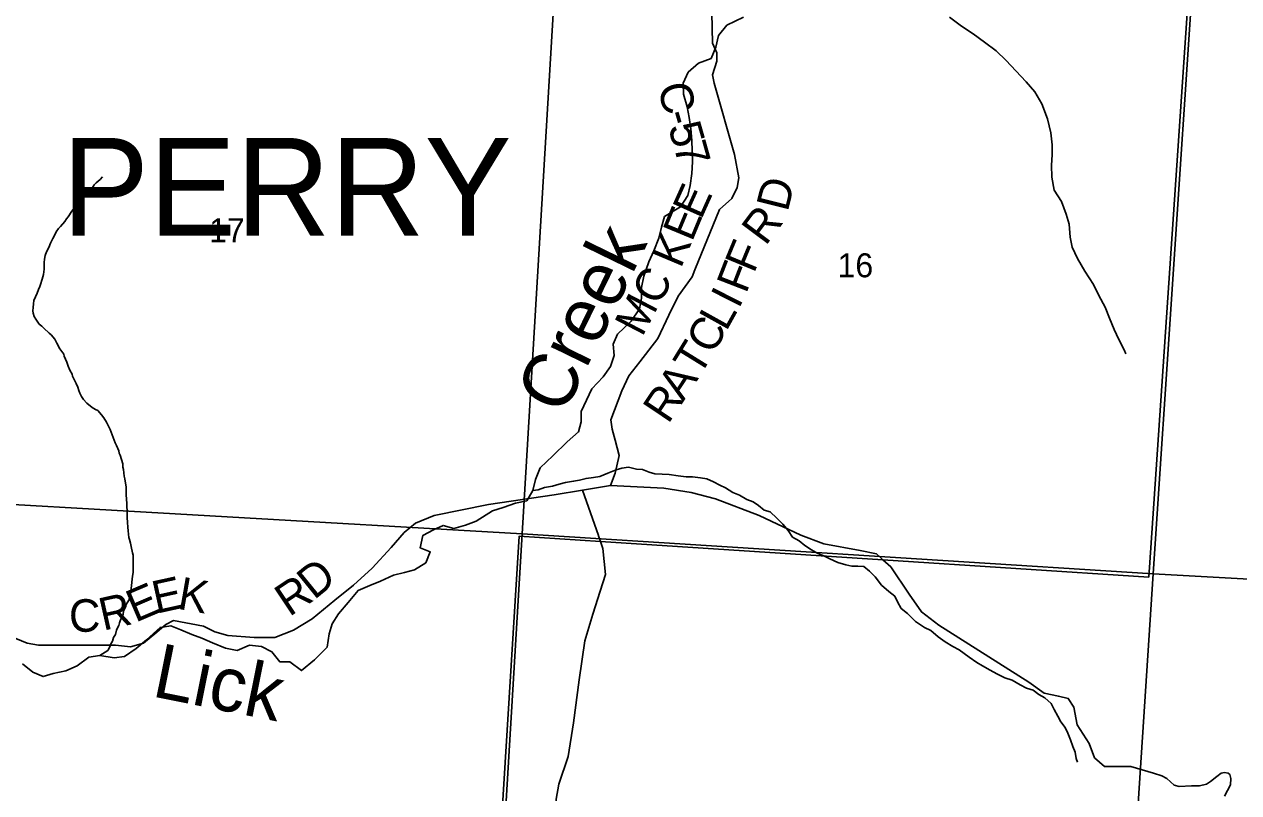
# Model space of a CAD drawing. Extents: x 1949938.81 to 1949945.61, y 152207.65 to 152214.09.
# Drawn here: x 1949940.583 to 1949942.704, y 152211.771 to 152213.113 of the extents above; entities that cross this region are included whole.
import ezdxf

# ---------------------------------------------------------------- set-up
doc = ezdxf.new("R2010")
doc.units = 0
for name, color, linetype in [('GM_X_County_Road', 7, 'Continuous'), ('GM_X_County_Road_Text', 7, 'Continuous'), ('GM_X_Minor_River', 7, 'Continuous'), ('GM_X_Minor_River_Text', 7, 'Continuous'), ('GM_X_Section', 7, 'Continuous'), ('GM_X_Section_Text', 7, 'Continuous'), ('GM_X_Township', 7, 'Continuous'), ('GM_X_Township_Road', 7, 'Continuous'), ('GM_X_Township_Text', 7, 'Continuous')]:
    doc.layers.add(name, color=color, linetype=linetype)

msp = doc.modelspace()

# ---------------------------------------------------------------- linework, layer by layer
at = {"layer": 'GM_X_County_Road'}
for points in [[(1949941.6066, 152212.3076), (1949941.6147, 152212.3293), (1949941.6219, 152212.3605), (1949941.6147, 152212.3869), (1949941.6099, 152212.4061), (1949941.6075, 152212.4228), (1949941.6267, 152212.4732), (1949941.6387, 152212.4996), (1949941.6579, 152212.5236), (1949941.6891, 152212.5644), (1949941.7083, 152212.6051), (1949941.7251, 152212.6387), (1949941.7371, 152212.6555), (1949941.7491, 152212.6723), (1949941.7539, 152212.6843), (1949941.7971, 152212.7898), (1949941.8186, 152212.809), (1949941.8282, 152212.8282), (1949941.8306, 152212.845), (1949941.8234, 152212.8857), (1949941.7875, 152213.0105), (1949941.7851, 152213.0248), (1949941.7923, 152213.0488), (1949941.7923, 152213.0632), (1949941.7851, 152213.08), (1949941.7823, 152213.1873)], [(1949940.5553, 152212.0457), (1949940.588, 152212.0326), (1949940.6077, 152212.0293), (1949940.742, 152212.0293), (1949940.7682, 152212.026), (1949940.7911, 152212.0326), (1949940.8107, 152212.049), (1949940.8304, 152212.0653), (1949940.8435, 152212.0719), (1949940.8959, 152212.0621), (1949940.9156, 152212.0522), (1949940.9385, 152212.0457), (1949940.9843, 152212.0424), (1949941.0204, 152212.0424), (1949941.0531, 152212.0555), (1949941.0859, 152212.0751), (1949941.1252, 152212.1079), (1949941.1579, 152212.1341), (1949941.1907, 152212.1636), (1949941.2234, 152212.1996), (1949941.2464, 152212.2258), (1949941.266, 152212.2421), (1949941.2988, 152212.2552), (1949941.3937, 152212.2749), (1949941.5084, 152212.2913), (1949941.558, 152212.2995), (1949941.6066, 152212.3076), (1949941.6998, 152212.3034), (1949941.7476, 152212.2958), (1949941.7898, 152212.2843), (1949941.8663, 152212.2556), (1949941.9391, 152212.2212), (1949941.9793, 152212.2058), (1949942.0425, 152212.1944), (1949942.0712, 152212.1886), (1949942.0825, 152212.1782), (1949942.0961, 152212.1657), (1949942.1285, 152212.1182)], [(1949942.1285, 152212.1182), (1949942.1497, 152212.0872), (1949942.1803, 152212.0642), (1949942.3373, 152211.9647), (1949942.3641, 152211.9455), (1949942.389, 152211.9398), (1949942.4062, 152211.936), (1949942.4158, 152211.9207), (1949942.4215, 152211.89), (1949942.4426, 152211.8575), (1949942.4522, 152211.8326), (1949942.4694, 152211.8173), (1949942.5153, 152211.8173), (1949942.5548, 152211.8056), (1949942.5695, 152211.8008), (1949942.5785, 152211.7965), (1949942.5909, 152211.7847), (1949942.5996, 152211.7821), (1949942.6214, 152211.7836), (1949942.6355, 152211.7836), (1949942.6476, 152211.7863), (1949942.6546, 152211.7913), (1949942.6654, 152211.7996), (1949942.6733, 152211.8054), (1949942.6791, 152211.8066), (1949942.6853, 152211.8058), (1949942.6882, 152211.8033), (1949942.6903, 152211.7963), (1949942.6895, 152211.7855), (1949942.6841, 152211.7751), (1949942.6787, 152211.7655)]]:
    msp.add_lwpolyline(points, dxfattribs=at)
at = {"layer": 'GM_X_Minor_River'}
for points in [[(1949940.7966, 152212.0381), (1949940.8202, 152212.06), (1949940.8391, 152212.063), (1949940.8565, 152212.0561), (1949940.8754, 152212.0477), (1949940.8928, 152212.0415), (1949940.9117, 152212.0331), (1949940.9344, 152212.0239), (1949940.9548, 152212.02), (1949940.9761, 152212.0291), (1949940.9973, 152212.0267), (1949941.0154, 152212.0175), (1949941.029, 152212), (1949941.0464, 152212), (1949941.0668, 152211.9847), (1949941.0896, 152212.0036), (1949941.1116, 152212.0255), (1949941.1155, 152212.0491), (1949941.1209, 152212.0665), (1949941.1315, 152212.0839), (1949941.1483, 152212.1036), (1949941.1658, 152212.1248), (1949941.1863, 152212.1331), (1949941.2052, 152212.1406), (1949941.228, 152212.1512), (1949941.247, 152212.1557), (1949941.2644, 152212.1609), (1949941.2842, 152212.173), (1949941.2918, 152212.1919), (1949941.2744, 152212.1988), (1949941.2791, 152212.2208), (1949941.2973, 152212.2306), (1949941.3147, 152212.2382), (1949941.3329, 152212.2328), (1949941.3534, 152212.2388), (1949941.3723, 152212.2456), (1949941.4004, 152212.2637), (1949941.4194, 152212.2697), (1949941.4406, 152212.2772), (1949941.4603, 152212.2809), (1949941.471, 152212.2991), (1949941.4756, 152212.3181), (1949941.484, 152212.3385), (1949941.5061, 152212.3597), (1949941.5312, 152212.3839), (1949941.5509, 152212.4013), (1949941.5556, 152212.4188), (1949941.5556, 152212.437), (1949941.574, 152212.4764), (1949941.5938, 152212.4976), (1949941.6067, 152212.5158), (1949941.6129, 152212.5347), (1949941.6114, 152212.5545), (1949941.6191, 152212.5719), (1949941.6426, 152212.5946), (1949941.6571, 152212.6166), (1949941.661, 152212.6348), (1949941.6611, 152212.6538), (1949941.6649, 152212.6735), (1949941.6734, 152212.6985), (1949941.6825, 152212.7175), (1949941.691, 152212.7395), (1949941.6956, 152212.7592), (1949941.701, 152212.7774), (1949941.7291, 152212.7947), (1949941.742, 152212.8144), (1949941.7459, 152212.8319), (1949941.749, 152212.8524), (1949941.7498, 152212.8729), (1949941.7492, 152212.8919), (1949941.7485, 152212.9101), (1949941.7471, 152212.9306), (1949941.7441, 152212.9503), (1949941.7404, 152212.9693), (1949941.7344, 152212.9914), (1949941.7338, 152213.0103), (1949941.7422, 152213.0293), (1949941.7604, 152213.0452), (1949941.7824, 152213.0534), (1949941.7908, 152213.0732), (1949941.7955, 152213.0936), (1949941.8099, 152213.1118), (1949941.8388, 152213.1254)], [(1949942.1985, 152213.1257), (1949942.2197, 152213.1097)], [(1949942.2197, 152213.1097), (1949942.24, 152213.0967), (1949942.2597, 152213.0822), (1949942.2801, 152213.067), (1949942.2974, 152213.0502), (1949942.3148, 152213.0319), (1949942.3329, 152213.0129), (1949942.3479, 152212.9954), (1949942.36, 152212.9741), (1949942.3697, 152212.9482), (1949942.3757, 152212.9239), (1949942.3778, 152212.9026), (1949942.3778, 152212.8852), (1949942.3769, 152212.867), (1949942.3776, 152212.8465), (1949942.3813, 152212.8237), (1949942.3941, 152212.8039), (1949942.4023, 152212.7818), (1949942.4075, 152212.7644), (1949942.4097, 152212.7416), (1949942.4127, 152212.7241), (1949942.4224, 152212.7043), (1949942.4352, 152212.6823), (1949942.4503, 152212.6587), (1949942.4593, 152212.6397), (1949942.4706, 152212.6191), (1949942.4781, 152212.6001), (1949942.4863, 152212.5804), (1949942.4946, 152212.5629), (1949942.5036, 152212.5446), (1949942.5066, 152212.5378)], [(1949940.7198, 152212.8469), (1949940.7152, 152212.842), (1949940.7082, 152212.8361), (1949940.7048, 152212.8327), (1949940.7013, 152212.8271), (1949940.6978, 152212.823), (1949940.6931, 152212.8173), (1949940.6858, 152212.8106), (1949940.6816, 152212.8069), (1949940.6781, 152212.8028), (1949940.675, 152212.7975), (1949940.6692, 152212.7915), (1949940.6661, 152212.787), (1949940.6595, 152212.7769), (1949940.6564, 152212.7735), (1949940.6536, 152212.769), (1949940.6463, 152212.76), (1949940.6428, 152212.7563), (1949940.6389, 152212.751), (1949940.637, 152212.7469), (1949940.6327, 152212.7394), (1949940.6287, 152212.7307), (1949940.6256, 152212.7232), (1949940.622, 152212.7156), (1949940.6193, 152212.7092), (1949940.618, 152212.7032), (1949940.6175, 152212.6975), (1949940.6178, 152212.6914), (1949940.6177, 152212.6853), (1949940.6164, 152212.6762), (1949940.6144, 152212.6683), (1949940.6112, 152212.6589), (1949940.6103, 152212.6551), (1949940.6076, 152212.6498), (1949940.6052, 152212.6434), (1949940.5997, 152212.6306), (1949940.5988, 152212.6249), (1949940.5983, 152212.6185), (1949940.5979, 152212.6131), (1949940.5985, 152212.6086), (1949940.6003, 152212.6032), (1949940.6029, 152212.5983), (1949940.6092, 152212.5894), (1949940.6137, 152212.5863), (1949940.617, 152212.5824), (1949940.6263, 152212.5736), (1949940.6297, 152212.5708), (1949940.636, 152212.5631), (1949940.6397, 152212.5562), (1949940.6448, 152212.5467), (1949940.6518, 152212.537), (1949940.6525, 152212.5336), (1949940.6573, 152212.5233), (1949940.6598, 152212.5164), (1949940.6627, 152212.5095), (1949940.6664, 152212.5022), (1949940.6671, 152212.4988), (1949940.6733, 152212.4862), (1949940.6762, 152212.4797), (1949940.6784, 152212.4736), (1949940.6802, 152212.469), (1949940.6827, 152212.4632), (1949940.6864, 152212.4582), (1949940.692, 152212.4517), (1949940.7013, 152212.4439), (1949940.7073, 152212.4404), (1949940.7111, 152212.4388), (1949940.7178, 152212.4315), (1949940.7218, 152212.4261), (1949940.7266, 152212.4184), (1949940.7332, 152212.4054), (1949940.7347, 152212.4012), (1949940.7365, 152212.3962), (1949940.7419, 152212.3825), (1949940.7441, 152212.3779), (1949940.7481, 152212.3683), (1949940.7488, 152212.3641), (1949940.7506, 152212.3607), (1949940.7549, 152212.3458), (1949940.7548, 152212.3397), (1949940.7562, 152212.3359), (1949940.7575, 152212.3241), (1949940.7586, 152212.3195), (1949940.7589, 152212.3153), (1949940.7606, 152212.3054), (1949940.7609, 152212.299), (1949940.7611, 152212.2914), (1949940.762, 152212.2762), (1949940.7623, 152212.2705), (1949940.7625, 152212.264), (1949940.7627, 152212.2522), (1949940.7633, 152212.2435), (1949940.7639, 152212.2351), (1949940.7642, 152212.2287), (1949940.7649, 152212.2229), (1949940.7655, 152212.2169), (1949940.7666, 152212.2134), (1949940.7687, 152212.2069), (1949940.7698, 152212.2016), (1949940.7719, 152212.1902), (1949940.7729, 152212.186)], [(1949941.471, 152212.2991), (1949941.4805, 152212.3), (1949941.4915, 152212.3045), (1949941.5055, 152212.3068), (1949941.5172, 152212.3102), (1949941.5282, 152212.3132), (1949941.5422, 152212.3154), (1949941.5524, 152212.3173), (1949941.5641, 152212.3203), (1949941.577, 152212.3218), (1949941.5879, 152212.3237), (1949941.6023, 152212.3294), (1949941.6167, 152212.3354), (1949941.6265, 152212.3381), (1949941.6379, 152212.3396), (1949941.6522, 152212.3365), (1949941.6628, 152212.3358), (1949941.6742, 152212.3312), (1949941.684, 152212.3285), (1949941.6972, 152212.3277), (1949941.7089, 152212.327), (1949941.7248, 152212.3247), (1949941.7388, 152212.3228), (1949941.7501, 152212.3227), (1949941.7638, 152212.3212), (1949941.7747, 152212.3193), (1949941.7868, 152212.314), (1949941.7974, 152212.3087), (1949941.8076, 152212.3037), (1949941.8201, 152212.2954), (1949941.8318, 152212.2912), (1949941.845, 152212.2836), (1949941.8556, 152212.2794), (1949941.8654, 152212.2729), (1949941.8753, 152212.2649), (1949941.8855, 152212.2619), (1949941.8972, 152212.2509), (1949941.9078, 152212.2406), (1949941.9168, 152212.2292), (1949941.9244, 152212.2178), (1949941.9361, 152212.211), (1949941.9463, 152212.203), (1949941.9577, 152212.1954), (1949941.969, 152212.1893), (1949941.9792, 152212.1848), (1949941.9898, 152212.1798), (1949942.0038, 152212.1734), (1949942.0178, 152212.1692), (1949942.0283, 152212.1669), (1949942.0386, 152212.1669), (1949942.0491, 152212.1665), (1949942.059, 152212.1585), (1949942.0692, 152212.1483), (1949942.0801, 152212.1338), (1949942.093, 152212.1228), (1949942.1032, 152212.1148), (1949942.1081, 152212.105), (1949942.1145, 152212.0932), (1949942.1255, 152212.0841), (1949942.1391, 152212.0704), (1949942.1553, 152212.0598), (1949942.1663, 152212.0544), (1949942.1788, 152212.0438), (1949942.1912, 152212.0351), (1949942.2048, 152212.0267), (1949942.2158, 152212.021), (1949942.2332, 152212.0081), (1949942.2464, 152211.999), (1949942.2562, 152211.9929), (1949942.2698, 152211.9857), (1949942.2812, 152211.9788), (1949942.2952, 152211.972), (1949942.3084, 152211.9678), (1949942.3224, 152211.9598), (1949942.3333, 152211.9541), (1949942.3447, 152211.9503), (1949942.3545, 152211.9427), (1949942.3655, 152211.937), (1949942.3761, 152211.9275), (1949942.3813, 152211.9169), (1949942.3881, 152211.9051), (1949942.3934, 152211.8952), (1949942.4006, 152211.8853), (1949942.4051, 152211.8755), (1949942.41, 152211.8637), (1949942.4142, 152211.8519), (1949942.4183, 152211.8421), (1949942.4202, 152211.8311), (1949942.4221, 152211.825)], [(1949940.7729, 152212.186), (1949940.7732, 152212.181), (1949940.7733, 152212.1624), (1949940.7731, 152212.156), (1949940.7719, 152212.1495), (1949940.7706, 152212.1393), (1949940.7701, 152212.1328), (1949940.7683, 152212.1196), (1949940.7675, 152212.1147), (1949940.7655, 152212.1079), (1949940.7608, 152212.1003), (1949940.76, 152212.0966), (1949940.7561, 152212.089), (1949940.7556, 152212.0826), (1949940.7532, 152212.0781), (1949940.7501, 152212.0713), (1949940.7492, 152212.0679), (1949940.748, 152212.0637), (1949940.7465, 152212.0603), (1949940.7441, 152212.055), (1949940.7425, 152212.0479), (1949940.7389, 152212.0422), (1949940.7369, 152212.0358), (1949940.7334, 152212.0302), (1949940.7322, 152212.026), (1949940.7287, 152212.0196), (1949940.7147, 152212.0111)], [(1949940.5798, 152211.9964), (1949940.5979, 152211.9819), (1949940.6161, 152211.9742), (1949940.6335, 152211.9795), (1949940.6555, 152211.984), (1949940.6752, 152211.993), (1949940.6957, 152212.0081), (1949940.7147, 152212.0111), (1949940.7397, 152212.0072), (1949940.7579, 152212.0094), (1949940.7784, 152212.023), (1949940.7966, 152212.0381)]]:
    msp.add_lwpolyline(points, dxfattribs=at)
at = {"layer": 'GM_X_Section'}
for points in [[(1949941.5133, 152213.2491), (1949941.4524, 152212.2232), (1949940.3609, 152212.2864), (1949940.4294, 152213.3146)], [(1949942.623, 152213.1832), (1949942.5545, 152212.1539), (1949941.4524, 152212.2232), (1949941.5133, 152213.2491)], [(1949943.7308, 152213.1166), (1949943.6665, 152212.0918), (1949942.5545, 152212.1539), (1949942.623, 152213.1832)], [(1949940.3609, 152212.2864), (1949941.4524, 152212.2232), (1949941.3926, 152211.2226), (1949940.2943, 152211.2945)], [(1949941.4524, 152212.2232), (1949942.5545, 152212.1539), (1949942.4891, 152211.1555), (1949941.3926, 152211.2226)], [(1949942.5545, 152212.1539), (1949943.6665, 152212.0918), (1949943.6063, 152211.0859), (1949942.4891, 152211.1555)]]:
    msp.add_lwpolyline(points, close=True, dxfattribs=at)
at = {"layer": 'GM_X_Township'}
for points in [[(1949942.6839, 152214.0874), (1949942.6751, 152213.9962), (1949942.6641, 152213.8415), (1949942.6215, 152213.2412), (1949942.6168, 152213.1758), (1949942.5466, 152212.148), (1949942.0825, 152212.1782), (1949941.5893, 152212.2102), (1949941.4472, 152212.2194), (1949941.3847, 152211.2124)], [(1949941.3847, 152211.2124), (1949941.4472, 152212.2194), (1949941.5893, 152212.2102), (1949942.0825, 152212.1782), (1949942.5466, 152212.148), (1949942.6168, 152213.1758), (1949942.6215, 152213.2412), (1949942.6641, 152213.8415), (1949942.6751, 152213.9962), (1949942.6839, 152214.0874)]]:
    msp.add_lwpolyline(points, dxfattribs=at)
at = {"layer": 'GM_X_Township_Road'}
for points in [[(1949941.5857, 152212.2205), (1949941.558, 152212.2995)], [(1949941.54, 152211.5769), (1949941.5332, 152211.6176), (1949941.5142, 152211.6605), (1949941.5078, 152211.7049), (1949941.512, 152211.7604), (1949941.5165, 152211.7866), (1949941.5328, 152211.8348), (1949941.5423, 152211.8936), (1949941.5521, 152211.9688), (1949941.562, 152212.0364), (1949941.5757, 152212.0831), (1949941.5889, 152212.1236), (1949941.598, 152212.1524), (1949941.5935, 152212.1981), (1949941.5893, 152212.2102), (1949941.5858, 152212.2202), (1949941.5857, 152212.2205)]]:
    msp.add_lwpolyline(points, dxfattribs=at)

# ---------------------------------------------------------------- texts
at = {"layer": 'GM_X_County_Road_Text'}
for s, rotation, p in [('C', 283.0308, (1949941.6891, 152213.0053)), ('-', 286.0474, (1949941.7005, 152212.9567)), ('5', 285.9904, (1949941.7069, 152212.9343)), ('7', 285.6604, (1949941.7165, 152212.9007)), ('E', 65.8064, (1949941.765, 152212.7707)), ('D', 75.9454, (1949941.9159, 152212.7842)), ('E', 67.5026, (1949941.7489, 152212.7319)), ('R', 53.1987, (1949941.8774, 152212.7248)), ('K', 67.1785, (1949941.7294, 152212.6855)), ('F', 67.4881, (1949941.8572, 152212.6768)), ('C', 60.4093, (1949941.6904, 152212.62)), ('F', 68.855, (1949941.8435, 152212.6413)), ('M', 62.4774, (1949941.6621, 152212.5658)), ('I', 63.0784, (1949941.8304, 152212.6148)), ('C', 60.4905, (1949941.7854, 152212.5346)), ('L', 60.9576, (1949941.8087, 152212.5756)), ('T', 58.2888, (1949941.7619, 152212.4964)), ('A', 56.779, (1949941.7336, 152212.4532)), ('R', 56.2249, (1949941.7073, 152212.4139)), ('D', 39.1121, (1949941.089, 152212.1071)), ('E', 23.1261, (1949940.7769, 152212.068)), ('E', 12.4015, (1949940.8133, 152212.0838)), ('K', 350.0485, (1949940.849, 152212.0928)), ('R', 33.8016, (1949941.0457, 152212.0778)), ('R', 12.6834, (1949940.7207, 152212.0542)), ('C', 0.9251, (1949940.6614, 152212.052))]:
    msp.add_text(s, height=0.0568, rotation=rotation, dxfattribs=at).set_placement(p)
at = {"layer": 'GM_X_Minor_River_Text'}
for s, height, rotation, p in [('Creek', 0.09468, 64.0091, (1949941.524, 152212.4278)), ('Lick', 0.0947, 348.6135, (1949940.8036, 152211.9402))]:
    msp.add_text(s, height=height, rotation=rotation, dxfattribs=at).set_placement(p)
at = {"layer": 'GM_X_Section_Text'}
for s, p in [('17', (1949940.9057, 152212.7327)), ('16', (1949942.0032, 152212.6714))]:
    msp.add_text(s, height=0.04186, rotation=0, dxfattribs=at).set_placement(p)
at = {"layer": 'GM_X_Township_Text'}
msp.add_text('PERRY', height=0.17045, rotation=0, dxfattribs=at).set_placement((1949940.6487, 152212.7442))

doc.saveas('drawing.dxf')
